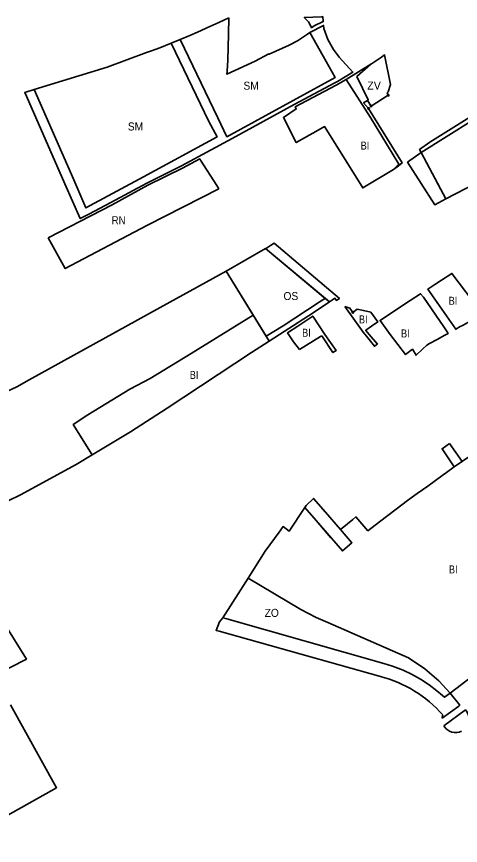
# Model space of a CAD drawing. Extents: x -650276 to -642489, y -1074311 to -1066658.
# Drawn here: x -648741 to -648077, y -1071627 to -1070387 of the extents above; entities that cross this region are included whole.
import ezdxf

# ---------------------------------------------------------------- set-up
doc = ezdxf.new("R2010")
doc.units = 0
doc.header["$LTSCALE"] = 4.8
doc.header["$PDMODE"] = 32
doc.header["$PDSIZE"] = 2.4
for name, color, linetype, lineweight in [('1', 7, 'Continuous', 35), ('15', 7, 'Continuous', 35), ('18', 7, 'Continuous', 35), ('2', 7, 'Continuous', 35), ('24', 7, 'Continuous', 35), ('40', 7, 'Continuous', 35), ('42', 7, 'Continuous', 35), ('7', 7, 'Continuous', 35), ('9', 7, 'Continuous', 35)]:
    doc.layers.add(name, color=color, linetype=linetype, lineweight=lineweight)
doc.layers.add('62', color=7, linetype='Continuous')
doc.layers.add('63', color=7, linetype='Continuous')

msp = doc.modelspace()

# ---------------------------------------------------------------- linework, layer by layer
at = {"layer": '1'}
msp.add_lwpolyline([(-648098.637, -1070659.682), (-648007.838, -1070612.851), (-648019, -1070518), (-648135.47, -1070590.61), (-648105.98, -1070645.91)], close=True, dxfattribs=at)
at = {"layer": '15'}
for p, q in [((-648303.631, -1070834.849), (-648283.19, -1070821.23)), ((-648272.453, -1070814.072), (-648271.1, -1070813.17))]:
    msp.add_line(p, q, dxfattribs=at)
for points in [[(-648303.705, -1070395.035), (-648302.028, -1070398.436), (-648299.32, -1070403.93), (-648295.18, -1070401.23), (-648281.907, -1070394.762), (-648282.582, -1070387.276), (-648284.37, -1070387.85), (-648310.275, -1070388.476)], [(-648550.72, -1070626.869), (-648636.757, -1070673.431), (-648655.178, -1070631.294), (-648714.161, -1070496.376), (-648728.255, -1070500.709), (-648725.835, -1070506.221), (-648668.207, -1070637.453), (-648645.331, -1070689.546), (-648632.652, -1070682.82), (-648599.66, -1070665.32), (-648545.76, -1070636.22), (-648494.04, -1070610.73), (-648417.855, -1070569.57), (-648325.21, -1070518.84), (-648264.56, -1070486.34), (-648260.57, -1070484.2), (-648237.475, -1070470.361), (-648257.96, -1070448.17), (-648266.416, -1070436.404), (-648274.808, -1070421.647), (-648280.974, -1070405.11), (-648281.388, -1070400.523), (-648302.01, -1070411.05), (-648282.01, -1070446.35), (-648263.859, -1070478.393), (-648425.835, -1070567.021), (-648439.409, -1070538.729), (-648495.666, -1070421.476), (-648509.227, -1070426.957), (-648452.97, -1070544.21), (-648440.531, -1070567.236)], [(-648007.838, -1070612.851), (-647999.588, -1070608.596), (-648002, -1070588), (-648010.831, -1070512.588), (-647999.756, -1070505.655), (-647981.81, -1070496.06), (-647950.48, -1070482.79), (-647917.98, -1070472.47), (-647918.54, -1070468.61), (-647918.95, -1070462.36), (-647923.53, -1070462.75), (-647923.247, -1070465.749), (-647953.251, -1070475.276), (-647985.19, -1070488.804), (-647991.539, -1070492.016), (-648005.668, -1070434.145), (-648014.63, -1070439.36), (-648000.442, -1070499.336), (-648019.789, -1070511.293), (-648050.38, -1070530.2), (-648122.57, -1070575), (-648137.78, -1070586.25), (-648135.47, -1070590.61), (-648019, -1070518)], [(-648135.47, -1070590.61), (-648155.582, -1070605.295), (-648115.057, -1070668.651), (-648098.637, -1070659.682)], [(-648092.72, -1071025.89), (-648104.12, -1071033.78), (-648085.73, -1071060.92), (-648074.12, -1071052.75)], [(-648238.84, -1071174.33), (-648256.04, -1071154.5), (-648278.39, -1071128.74), (-648296.34, -1071108.04), (-648307.33, -1071118.47), (-648309.41, -1071121.655), (-648292.587, -1071141.054), (-648270.236, -1071166.815), (-648253.126, -1071186.542)]]:
    msp.add_lwpolyline(points, close=True, dxfattribs=at)
for points in [[(-648213.87, -1070524.8), (-648221.359, -1070516.349), (-648215.48, -1070512.59), (-648214.34, -1070511.86), (-648231.53, -1070476.99), (-648210.48, -1070458.42), (-648247.67, -1070481.57), (-648211, -1070538), (-648168.575, -1070607.847), (-648176.54, -1070616.09)], [(-648176.54, -1070616.09), (-648169.28, -1070610.49), (-648163.8, -1070606.27), (-648213.87, -1070524.8), (-648221.359, -1070516.349), (-648215.48, -1070512.59), (-648214.34, -1070511.86), (-648231.53, -1070476.99), (-648210.48, -1070458.42), (-648247.67, -1070481.57), (-648211, -1070538)], [(-648176.54, -1070616.09), (-648169.28, -1070610.49), (-648163.8, -1070606.27), (-648213.87, -1070524.8)], [(-648211, -1070538), (-648168.575, -1070607.847), (-648176.54, -1070616.09)], [(-648271.1, -1070813.17), (-648267.8, -1070810.96), (-648264.38, -1070808.66), (-648262.15, -1070811.96), (-648257.61, -1070808.91), (-648355.275, -1070726.455), (-648360.83, -1070729.87), (-648366.739, -1070733.501), (-648368.163, -1070734.376), (-648272.453, -1070814.072)], [(-648283.19, -1070821.23), (-648272.45, -1070814.075), (-648278.832, -1070808.761), (-648282.44, -1070810.84), (-648287.74, -1070814.32)], [(-648287.74, -1070814.32), (-648341.58, -1070849.98), (-648366.98, -1070865.44)], [(-648366.98, -1070865.44), (-648362.519, -1070872.788), (-648303.631, -1070834.849)]]:
    msp.add_lwpolyline(points, dxfattribs=at)
msp.add_point((-648213.87, -1070524.8), dxfattribs=at)
at = {"layer": '18'}
for points in [[(-648423.005, -1070389.357), (-648438.21, -1070396.22), (-648455.85, -1070404.19), (-648457.94, -1070405.13), (-648469.77, -1070410.47)], [(-648363.1, -1070443.1), (-648383.61, -1070453.86), (-648426.05, -1070473.34), (-648425.71, -1070468.87), (-648424.47, -1070452.7), (-648423.56, -1070413.35), (-648423.005, -1070389.357)], [(-648469.77, -1070410.47), (-648481.18, -1070415.62), (-648495.666, -1070421.476), (-648439.409, -1070538.729)], [(-648439.409, -1070538.729), (-648425.835, -1070567.021), (-648263.859, -1070478.393), (-648282.01, -1070446.35), (-648302.01, -1070411.05)], [(-648302.01, -1070411.05), (-648305.39, -1070413.38), (-648320.24, -1070423.64), (-648332.97, -1070430.18), (-648362.79, -1070443.63), (-648363.1, -1070443.1)]]:
    msp.add_lwpolyline(points, dxfattribs=at)
msp.add_lwpolyline([(-648636.757, -1070673.431), (-648550.72, -1070626.869), (-648440.531, -1070567.236), (-648452.97, -1070544.21), (-648509.227, -1070426.957), (-648526.28, -1070433.85), (-648538.611, -1070438.388), (-648546.377, -1070441.246), (-648604.92, -1070462.79), (-648714.161, -1070496.376), (-648655.178, -1070631.294)], close=True, dxfattribs=at)
at = {"layer": '2'}
for points in [[(-648247.67, -1070481.57), (-648262.69, -1070489.67), (-648323.59, -1070522.48), (-648322.18, -1070525.44), (-648341.41, -1070538.42), (-648322.16, -1070575.76), (-648289.22, -1070557.15), (-648279.736, -1070551.783), (-648278.89, -1070553.14), (-648222.58, -1070643.48), (-648176.54, -1070616.09), (-648168.575, -1070607.847), (-648211, -1070538)], [(-648114.77, -1070788.08), (-648125.2, -1070794.79), (-648083.65, -1070854.89), (-648076.73, -1070851.07), (-648074.41, -1070849.79), (-648072.59, -1070848.79), (-648065.35, -1070844.8), (-648061.52, -1070842.68), (-648063.76, -1070839.49), (-648056.61, -1070834.26), (-648047.17, -1070827.35), (-648089.27, -1070771.57), (-648104.78, -1070781.65)], [(-648167.6, -1070822.53), (-648196.65, -1070841.7), (-648181.75, -1070862.74), (-648158.58, -1070892.98), (-648148.34, -1070884.92), (-648142.79, -1070893.78), (-648133.14, -1070884.6), (-648127, -1070878.75), (-648122.72, -1070876.44), (-648111.24, -1070870.11), (-648099.85, -1070863.82), (-648094.9, -1070861.09), (-648095.42, -1070860.3), (-648101.45, -1070851.34), (-648132.03, -1070807.05), (-648136.08, -1070801.79), (-648151.77, -1070812.11)], [(-648540.7, -1070928.6), (-648571.14, -1070944.67), (-648634.07, -1070983.17), (-648655.76, -1070997.5), (-648627.39, -1071042.65), (-648605.3, -1071029.34), (-648570.23, -1071008.2), (-648515.46, -1070972.94), (-648389.33, -1070889.79), (-648362.519, -1070872.788), (-648386.587, -1070833.807), (-648479.18, -1070891.26)]]:
    msp.add_lwpolyline(points, close=True, dxfattribs=at)
for points in [[(-648237.46, -1070829.68), (-648241.96, -1070823.46), (-648249.5, -1070821.08)], [(-648249.5, -1070821.08), (-648222.158, -1070859.221), (-648217.1, -1070865.56), (-648205.18, -1070880.5), (-648200.86, -1070877.05)], [(-648210.517, -1070829.445), (-648221.58, -1070827.03), (-648231.22, -1070824.92), (-648237.46, -1070829.68)], [(-648284.02, -1070864.91), (-648267.24, -1070889.9), (-648262.4, -1070886.58), (-648279.39, -1070862.98), (-648297.39, -1070835.36), (-648320.02, -1070850.16), (-648335.19, -1070860.49), (-648326.41, -1070873.55), (-648317.14, -1070885.48)], [(-648218.11, -1070856.44), (-648209.37, -1070850.44), (-648200.17, -1070844.094), (-648210.517, -1070829.445)], [(-648200.86, -1070877.05), (-648212.94, -1070862.74), (-648217.85, -1070856.93), (-648218.11, -1070856.44)], [(-648317.14, -1070885.48), (-648285.72, -1070865.96), (-648284.02, -1070864.91)], [(-648062.53, -1071044.59), (-648085.73, -1071060.92), (-648097.61, -1071069.37), (-648102.55, -1071072.86), (-648125.53, -1071089.51), (-648141.12, -1071100.71), (-648155.77, -1071111.23), (-648172.48, -1071123.95), (-648197.57, -1071143.03), (-648215.08, -1071156.35), (-648232.8, -1071135.6), (-648237.46, -1071139.38), (-648245.49, -1071145.91), (-648256.04, -1071154.5), (-648238.84, -1071174.33), (-648253.126, -1071186.542), (-648292.587, -1071141.054), (-648309.41, -1071121.655), (-648333.002, -1071157.07), (-648341.943, -1071150.071), (-648347.949, -1071158.385), (-648368.48, -1071186.81), (-648394.104, -1071227.17), (-648315.127, -1071274.052), (-648292.406, -1071286.112), (-648274.918, -1071293.751), (-648154.21, -1071346.477), (-648130, -1071363), (-648109, -1071381), (-648091.92, -1071399.07), (-648060.01, -1071374.69)], [(-648764.17, -1071286.65), (-648725.85, -1071348.28), (-648774.371, -1071372.773)], [(-648749.854, -1071416.727), (-648680.709, -1071540.691), (-648835.095, -1071627.059)]]:
    msp.add_lwpolyline(points, dxfattribs=at)
msp.add_point((-648237.46, -1070829.68), dxfattribs=at)
at = {"layer": '24'}
for points in [[(-648103.894, -1071436.836), (-648079.108, -1071418.564), (-648077.53, -1071417.4), (-648091.92, -1071399.07), (-648100.438, -1071405.517), (-648103.268, -1071402.88), (-648111.646, -1071395.618), (-648123.313, -1071386.696), (-648136.263, -1071378.194), (-648149.571, -1071370.788), (-648162.084, -1071364.918), (-648178.158, -1071358.781), (-648191.25, -1071354.858), (-648426.18, -1071288.32), (-648432.093, -1071286.645), (-648437.16, -1071292.53), (-648442.191, -1071305.453), (-648437.454, -1071306.778), (-648196.236, -1071374.226)], [(-648063.593, -1071439.723), (-648063.862, -1071435.078), (-648064.838, -1071431.28), (-648066.623, -1071427.592), (-648069.022, -1071424.443), (-648101.203, -1071448.31)], [(-648101.203, -1071448.31), (-648098.259, -1071452.196), (-648096.014, -1071454.192), (-648093.059, -1071456.066), (-648089.539, -1071457.489), (-648085.585, -1071458.248), (-648081.642, -1071458.215), (-648078.539, -1071457.636), (-648074.86, -1071456.248)]]:
    msp.add_lwpolyline(points, dxfattribs=at)
for centre, radius, start, end in [((-648244.965, -1071557.871), 190, 41.59858, 75.13936), ((-648083.781, -1071438.172), 20.157, 161.35794, 176.20098)]:
    msp.add_arc(centre, radius, start, end, dxfattribs=at)
at = {"layer": '40'}
msp.add_line((-648210.19, -1070521.07), (-648184.54, -1070505.07), dxfattribs=at)
for points in [[(-648184.54, -1070505.07), (-648186.088, -1070501.313), (-648184.791, -1070500.073), (-648181.386, -1070488.724), (-648189.93, -1070444.71), (-648194.56, -1070447.8), (-648194.56, -1070447.799), (-648209.82, -1070457.98), (-648210.48, -1070458.42), (-648231.53, -1070476.99), (-648214.34, -1070511.86)], [(-648214.34, -1070511.86), (-648215.48, -1070512.59), (-648210.19, -1070521.07)]]:
    msp.add_lwpolyline(points, dxfattribs=at)
for p in [(-648184.54, -1070505.07), (-648210.19, -1070521.07)]:
    msp.add_point(p, dxfattribs=at)
at = {"layer": '42'}
msp.add_line((-648394.104, -1071227.17), (-648432.093, -1071286.645), dxfattribs=at)
for points in [[(-648292.406, -1071286.112), (-648315.127, -1071274.052), (-648394.104, -1071227.17), (-648432.093, -1071286.645)], [(-648432.093, -1071286.645), (-648426.18, -1071288.32), (-648191.25, -1071354.858)], [(-648091.92, -1071399.07), (-648109, -1071381), (-648130, -1071363), (-648154.21, -1071346.477), (-648274.918, -1071293.751), (-648292.406, -1071286.112)], [(-648191.25, -1071354.858), (-648178.158, -1071358.781), (-648162.084, -1071364.918), (-648149.571, -1071370.788), (-648136.263, -1071378.194), (-648123.313, -1071386.696), (-648111.646, -1071395.618), (-648103.268, -1071402.88), (-648100.438, -1071405.517), (-648091.92, -1071399.07)]]:
    msp.add_lwpolyline(points, dxfattribs=at)
at = {"layer": '7'}
for points in [[(-648438.13, -1070644.73), (-648440.8, -1070639.72), (-648465.28, -1070602.24), (-648466.61, -1070600.21), (-648492.47, -1070614.2), (-648544.42, -1070639.42), (-648597.74, -1070668.62), (-648693.45, -1070718.46)], [(-648693.45, -1070718.46), (-648667.72, -1070764.15), (-648574.27, -1070714.5), (-648544.906, -1070699.451), (-648438.13, -1070644.73)]]:
    msp.add_lwpolyline(points, dxfattribs=at)
msp.add_lwpolyline([(-648866.341, -1071000.881), (-648828.353, -1071043.265), (-648785.386, -1071084.634), (-648758.423, -1071107.756), (-648752.967, -1071111.861), (-648734.849, -1071102.599), (-648651.375, -1071057.109), (-648627.39, -1071042.65), (-648655.76, -1070997.5), (-648634.07, -1070983.17), (-648571.14, -1070944.67), (-648540.7, -1070928.6), (-648479.18, -1070891.26), (-648386.587, -1070833.807), (-648427.25, -1070767.95), (-648511.09, -1070814.7), (-648721.54, -1070930.88), (-648740.25, -1070941.21), (-648774.23, -1070956.42)], close=True, dxfattribs=at)
at = {"layer": '9'}
msp.add_lwpolyline([(-648368.163, -1070734.376), (-648427.25, -1070767.95), (-648366.98, -1070865.44), (-648341.58, -1070849.98), (-648287.74, -1070814.32), (-648282.44, -1070810.84), (-648278.832, -1070808.761)], close=True, dxfattribs=at)

# ---------------------------------------------------------------- texts
at = {"layer": '62'}
msp.add_text('ZV', height=12, dxfattribs=at).set_placement((-648216.069, -1070496.39))
for s, width, p in [('SM', 0.95, (-648574.138, -1070557.646)), ('BI', 0.85, (-648225.838, -1070586.256)), ('RN', 0.9, (-648598.428, -1070697.883)), ('OS', 0.95, (-648341.265, -1070811.272)), ('BI', 0.85, (-648094.127, -1070818.398)), ('BI', 0.85, (-648228.397, -1070846.265)), ('BI', 0.85, (-648313.397, -1070866.265)), ('BI', 0.85, (-648165.397, -1070867.265)), ('BI', 0.85, (-648481.397, -1070929.265)), ('BI', 0.85, (-648093.764, -1071220.263)), ('ZO', 0.95, (-648369.423, -1071285.188))]:
    msp.add_text(s, height=12, dxfattribs=dict(at, width=width)).set_placement(p)
at = {"layer": '63', "width": 0.95}
msp.add_text('SM', height=12, dxfattribs=at).set_placement((-648401.138, -1070496.646))

doc.saveas('drawing.dxf')
